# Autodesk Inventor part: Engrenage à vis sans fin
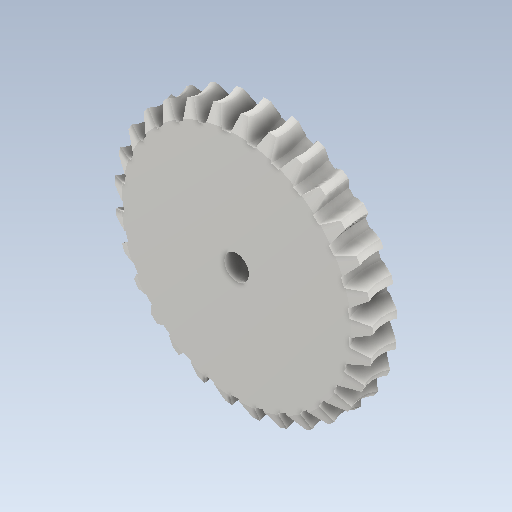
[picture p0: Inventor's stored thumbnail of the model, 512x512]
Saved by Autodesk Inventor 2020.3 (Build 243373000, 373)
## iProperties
CustomPartVersion: 1
Created: 2020-11
Part Number: Engrenage à vis sans fin
Material: Steel, Mild
Document SubType Name: Modeling
Designer: ficho
Categories: <?xml version="1.0" encoding="UTF-16"?> <MemberInstance><Categories><FamilyTemplate><FamilyTemplateParameter ValueType="xs:double" Id="1" ObjectReferenceKey="da
Density: 7.85 g/cm^3
Appearance: Steel
Mass: 6.94824 g
Surface Area: 9.5235 cm^2
Volume: 0.885126 cm^3
Author: ficho
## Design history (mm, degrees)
body "Solid1"
node "Plan de la dent"
sketch "Esquisse du corps de base"
  geometry: L1 (0, -2.717)-(0, 2.717) reference; L2 (0, 1.575)-(9.31, 1.575); L3 (9.31, 1.575)-(10.56, 0.958); L4 (-2.888, 0)-(17.329, 0) reference; L5 (10.56, 0.958)-(10.56, -0.958); L6 (0, -1.575)-(9.31, -1.575); L7 (0, 1.575)-(0, -1.575); L8 (9.31, -1.575)-(10.56, -0.958); C1 r 2.264 at (12.5, 0)
  constraints: 14 end point, 3 symmetric about line, 2 perpendicular, 2 point on line, 1 centre point, 1 collinear
  dimensions: "d50" = 26.2785 deg angle of L3 L2 (= da_fi); "d87" = 21.11917 diameter of L5 L1 (= da_dae); "d89" = 4.52764 diameter of C1 (= 2 x da_aw - da_da); "d92" = 3.15 distance of L2.start L6.start (= da_b); "d93" = 12.5 distance from line of C1.centre L7 (= da_aw)
revolve "Corps de base" stored, may be unused: angle "d35" = 90 deg
revolve "Corps de base 2" stored, may be unused: angle "d90" = 90 deg
workplane "Work Plane13"
revolve "Dent" stored, may be unused: angle "d43" = 90 deg
pattern_circular "Motif de la dent" dims angle "d46" = 360 deg
workplane "Work Plane14"
workplane "Work Plane15"
sketch "Esquisse9"
  geometry: 1 further point
hole "Perçage3" sketch "Esquisse9" diameter "d94" = 2; stored, may be unused: countersink angle "d98" = 90 deg, drill point angle "d100" = 118 deg; dims "d95" = 6, "d96" = 4, "d97" = 2, "d99" = 8
sketch "Esquisse de la dent"
  geometry: L1 (10, 1.256)-(10, -1.256) reference; L2 (-3.173, 0)-(1.536, 0) reference; L3 (-2.5, 0.896)-(-2.5, -0.896); L4 (-2.5, -0.896)-(-0.366, -0.896); L5 (-0.366, -0.896)-(1.187, -0.331); L6 (1.187, -0.331)-(1.187, 0); L7 (1.187, 0.331)-(-0.366, 0.896); L8 (-0.366, 0.896)-(-2.5, 0.896); L9 (1.187, 0.331)-(1.187, 0); L10 (0.411, 0)-(0.411, -0.613)
  constraints: 16 end point, 4 perpendicular, 3 equal length, 2 point on line, 1 midpoint, 1 parallel, 1 vertical
  dimensions: "d38" = 12.5 distance between parallel lines of L1 L3 (= da_aw); "d39" = 20 deg angle of L7 L8 (= da_alfat); "d40" = 2.13446 distance of L7.end L3.start (= 0.5 x da_df1); "d41" = 2.91063 distance between parallel lines of L3 L10 (= 0.5 x da_d1); "d42" = 0.6134 distance of L10.start L10.end (= 0.3 x da_px)
sketch "Sketch8"
  geometry: C1 r 9.31 at (0, 0) reference; C2 r 9.437 at (0, 0)
  constraints: 1 centre point, 1 coincident
  dimensions: "d77" = 18.87423 diameter of C2 (= da_dw)
body "Srf1"
feature "Diamètre primitif" dims "d78" = 3.15 (= da_b), "d79" = 0
other parameters: "da_aw" = 12.5 [user parameter; used in 5 equation terms], "da_fi" = 26.2785 deg [user parameter; used in 1 equation term], "da_b" = 3.15 [user parameter; used in 2 equation terms], "da_df" = 17.62642 [user parameter], "da_da" = 20.47236 [user parameter; used in 1 equation term], "da_beta" = 1.11341 [user parameter; used in 1 equation term], "da_alfat" = 20 deg [user parameter; used in 1 equation term], "da_df1" = 4.26892 [user parameter; used in 1 equation term], "da_da1" = 7.11486 [user parameter], "da_d1" = 5.82125 [user parameter; used in 1 equation term], "da_px" = 2.04466 [user parameter; used in 1 equation term], "d37" = -1.11341 (computed from da_rightdir, da_beta), "d68" = 12.5 (= da_aw), "d69" = 0, "d73" = 0, "d75" = 1.08331 (computed from da_z), "da_dw" = 18.87423 [user parameter; used in 1 equation term], "da_rightdir" = 0 [user parameter; used in 1 equation term], "d80" = 0, "d81" = 0, "d82" = 0, "d83" = 1.08331 (computed from da_z), "d84" = 0, "d85" = 180 deg, "d86" = 12.5 (= da_aw), "da_dae" = 21.11917 [user parameter; used in 1 equation term]
